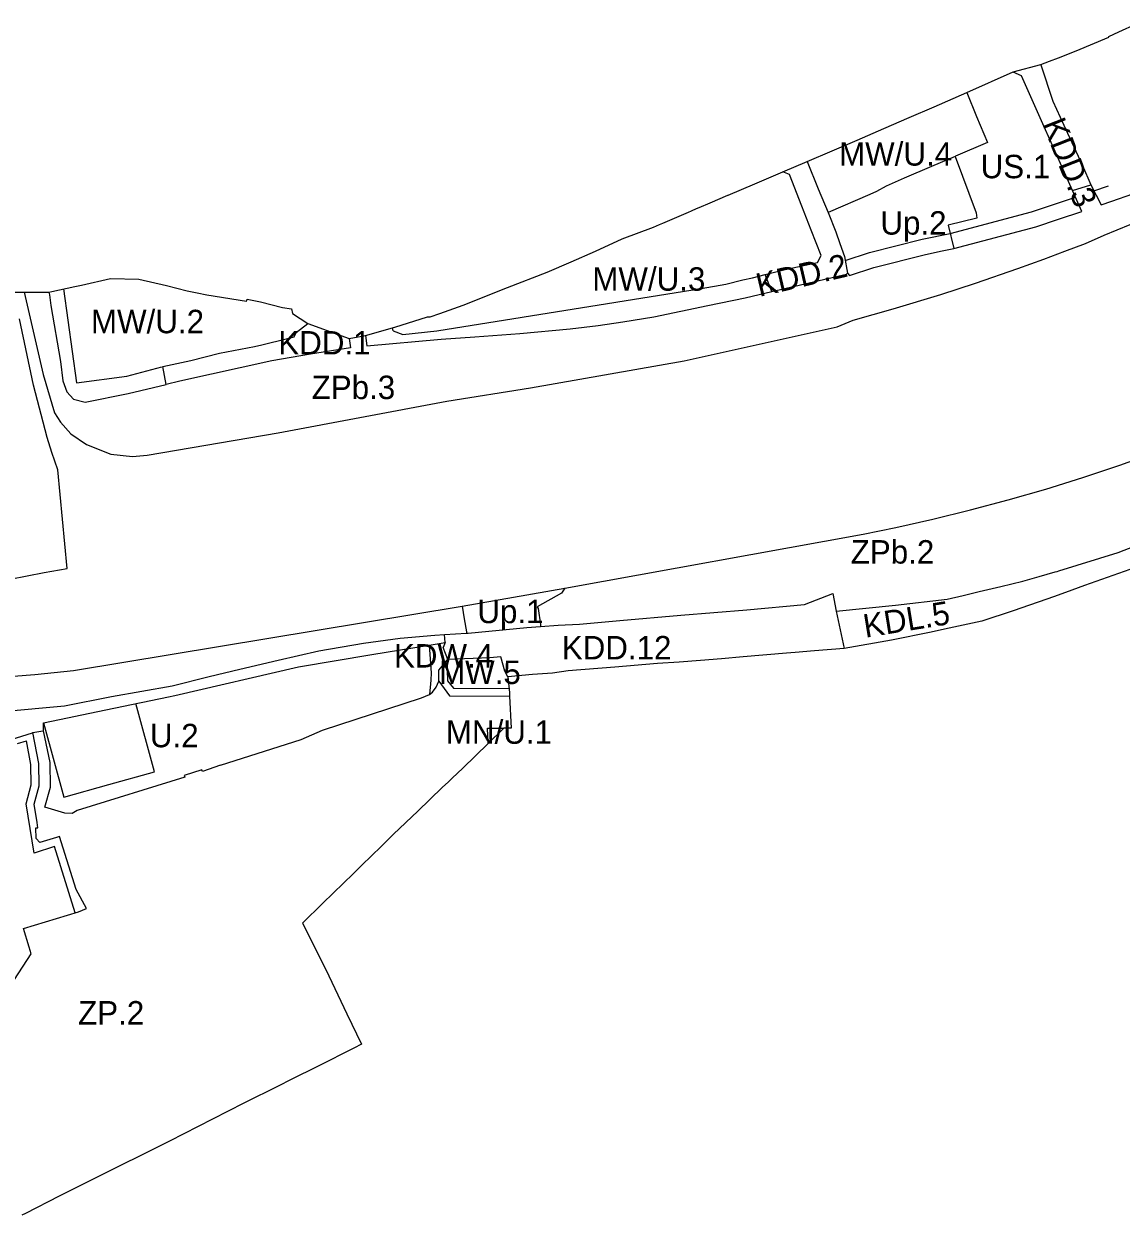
# Model space of a CAD drawing. Extents: x 7421697 to 7426767, y 5545731 to 5547485.
# Drawn here: x 7422364 to 7422926, y 5546353 to 5546963 of the extents above; entities that cross this region are included whole.
import ezdxf

# ---------------------------------------------------------------- set-up
doc = ezdxf.new("R2010")
doc.units = 0
for name, color, linetype in [('LIN_Linia Zabudowy Nieprzekraczalna', 7, 'Continuous'), ('LIN_linie_rozgraniczajace', 7, 'Continuous'), ('TXT_oznaczenia_przeznaczen', 7, 'Continuous')]:
    doc.layers.add(name, color=color, linetype=linetype)

msp = doc.modelspace()

# ---------------------------------------------------------------- linework, layer by layer
at = {"layer": 'LIN_Linia Zabudowy Nieprzekraczalna'}
for p, q in [((7422552.95, 5546806.17), (7422552.52, 5546807.68)), ((7422430.58, 5546580.08), (7422421.03, 5546615.08)), ((7422373.64, 5546605.22), (7422384.13, 5546567.15)), ((7422379.38, 5546541.92), (7422368.99, 5546538.42))]:
    msp.add_line(p, q, dxfattribs=at)
for points in [[(7422912.02, 5546877.8), (7422919.45, 5546880.48)], [(7422784.56, 5546842.21), (7422797.01, 5546846.25), (7422823.98, 5546853.04), (7422838.37, 5546856.05), (7422879.96, 5546867.06), (7422902.55, 5546874.63)], [(7422552.95, 5546806.17), (7422557.83, 5546804.33), (7422575.31, 5546806.09), (7422710.7, 5546827.9), (7422723.35, 5546830.03), (7422732.14, 5546832.22), (7422737.06, 5546833.31), (7422743.59, 5546835.05)], [(7422383.97, 5546827.59), (7422390.58, 5546779.45), (7422416.35, 5546782.97), (7422434.41, 5546787.75)], [(7422580.36, 5546637.67), (7422580.72, 5546626.73), (7422583.84, 5546623.03), (7422612.6, 5546622.89)], [(7422360.46, 5546594.59), (7422365.03, 5546596.05)], [(7422364.77, 5546563.74), (7422367.44, 5546573.55), (7422367.3, 5546583.97), (7422365.03, 5546596.05)], [(7422384.13, 5546567.15), (7422407.22, 5546573.65), (7422430.57, 5546580.08)], [(7422368.99, 5546538.42), (7422364.77, 5546563.74)], [(7422390.01, 5546507.84), (7422379.38, 5546541.92)]]:
    msp.add_lwpolyline(points, dxfattribs=at)
at = {"layer": 'LIN_linie_rozgraniczajace'}
for p, q in [((7422901.03, 5546878.01), (7422910.42, 5546880.92)), ((7422779.9, 5546662.45), (7422783.95, 5546643.35)), ((7422579.51, 5546646.49), (7422579.25, 5546650.51)), ((7422371.29, 5546584.37), (7422368.33, 5546600.22)), ((7422369.8, 5546551.45), (7422370.87, 5546551.46)), ((7422390.46, 5546519.82), (7422381.98, 5546547.01)), ((7422395.72, 5546510.16), (7422390.46, 5546519.82)), ((7422391.68, 5546508.35), (7422395.72, 5546510.16))]:
    msp.add_line(p, q, dxfattribs=at)
for points in [[(7422359.29, 5546825.98), (7422363.8, 5546825.99), (7422376.48, 5546826.02), (7422378.01, 5546826.34), (7422389.74, 5546828.8), (7422393.14, 5546829.48), (7422408.11, 5546832.87), (7422422.58, 5546832.59), (7422436.82, 5546829.38), (7422447.42, 5546826.65), (7422452.4, 5546825.55), (7422457.34, 5546824.66), (7422477.74, 5546821.31), (7422478.02, 5546822.34), (7422484.9, 5546820.92), (7422496.12, 5546818.14), (7422500.8, 5546817.39), (7422501.28, 5546814.95), (7422509.19, 5546809.96), (7422530.44, 5546802.24), (7422538.71, 5546803.82), (7422553.82, 5546808.04), (7422570.53, 5546813.32), (7422571.82, 5546813.37), (7422576.76, 5546815), (7422588.81, 5546819.33), (7422611.54, 5546828.37), (7422631.89, 5546836.15), (7422644.16, 5546841.41), (7422656.62, 5546847.04), (7422670.27, 5546853.34), (7422686.29, 5546859.23), (7422689.43, 5546860.59), (7422691.06, 5546861.3), (7422704.19, 5546866.92), (7422705.7, 5546867.58), (7422708.41, 5546868.77), (7422709.75, 5546869.36), (7422715.28, 5546871.67), (7422715.38, 5546871.71), (7422724.4, 5546875.59), (7422724.5, 5546875.63), (7422738.29, 5546881.5), (7422752.61, 5546887.69), (7422765.06, 5546892.92), (7422790.59, 5546903.9), (7422804.42, 5546909.82), (7422817.34, 5546915.4), (7422830.16, 5546920.97), (7422846.82, 5546928.26), (7422870.58, 5546938.86), (7422884.74, 5546942.56), (7422889.21, 5546944.29), (7422889.26, 5546944.31), (7422893.83, 5546946.09), (7422902.85, 5546949.59), (7422919.59, 5546956.68), (7422919.57, 5546956.95), (7422924.7, 5546959.3), (7422933.83, 5546963.46)], [(7422884.74, 5546942.56), (7422884.81, 5546942.53), (7422890.88, 5546923.79), (7422896.53, 5546911.48), (7422899.44, 5546905.2), (7422906.1, 5546890.86), (7422910.42, 5546880.92), (7422915.71, 5546870.63)], [(7422765.06, 5546892.92), (7422770.75, 5546878.85), (7422775.74, 5546866.79), (7422779.75, 5546856.85), (7422781.84, 5546850.87), (7422784.17, 5546844.28), (7422785.78, 5546835.69), (7422786.67, 5546834.48), (7422799.22, 5546838.56), (7422825.77, 5546845.24), (7422834.31, 5546847.09), (7422840.21, 5546848.26), (7422882.26, 5546859.4), (7422893.76, 5546863.43), (7422905.84, 5546867.3), (7422901.03, 5546878.01), (7422874.81, 5546936.78), (7422870.54, 5546938.73), (7422870.58, 5546938.86)], [(7422906.35, 5546730.92), (7422925.3, 5546737.28), (7422944.22, 5546744.12), (7422962.85, 5546751.36), (7422981.56, 5546758.6), (7422999.8, 5546766.68), (7423018.04, 5546775), (7423037.74, 5546784.62), (7423055.52, 5546793.71), (7423073.17, 5546803.13), (7423090.57, 5546813), (7423107.42, 5546822.96), (7423176.11, 5546867.28), (7423238.37, 5546907.25), (7423275.73, 5546929.87)], [(7422846.82, 5546928.26), (7422851.87, 5546915.91), (7422857.54, 5546902.7), (7422841.02, 5546895.7), (7422840.88, 5546895.5), (7422828.7, 5546890.35), (7422814.81, 5546884.37), (7422805.53, 5546880.21), (7422800.53, 5546877.51), (7422797.12, 5546876.03), (7422775.74, 5546866.79)], [(7422840.88, 5546895.5), (7422851.68, 5546866.61), (7422851.97, 5546863.82), (7422837.23, 5546860.28), (7422840.21, 5546848.26)], [(7422538.71, 5546803.82), (7422539.44, 5546798.41), (7422577.53, 5546801.85), (7422594.76, 5546803.09), (7422617.85, 5546804.8), (7422643.63, 5546807.12), (7422657.97, 5546808.95), (7422670.57, 5546810.7), (7422686.44, 5546813.39), (7422714.11, 5546819.07), (7422733.35, 5546823.01), (7422746.93, 5546826.21), (7422745.61, 5546829.77), (7422743.59, 5546835.05), (7422753.83, 5546837.53), (7422770.36, 5546841.15), (7422772.16, 5546844.67), (7422767.06, 5546857.65), (7422762.38, 5546869.96), (7422755.94, 5546886.18), (7422752.61, 5546887.69)], [(7422915.71, 5546870.63), (7422921.17, 5546872.55), (7422931.97, 5546876.36)], [(7422363.8, 5546825.99), (7422373.61, 5546783.76), (7422379.4, 5546764.19), (7422382.45, 5546759.31), (7422387.65, 5546753.42), (7422395.68, 5546747.84), (7422408.19, 5546742.89), (7422419.35, 5546741.69), (7422426.92, 5546742.5), (7422494.01, 5546753.83), (7422580.32, 5546770.04), (7422623.27, 5546776.99), (7422701.98, 5546790.69), (7422780.43, 5546808.14), (7422788.69, 5546811.54), (7422809.16, 5546817.39), (7422833.5, 5546824.82), (7422851.24, 5546830.53), (7422872.94, 5546838.07), (7422886.3, 5546842.92), (7422897.09, 5546846.92), (7422907.65, 5546850.84), (7422917.18, 5546855.08), (7422930.57, 5546860.54)], [(7422746.93, 5546826.21), (7422785.18, 5546835.19), (7422785.78, 5546835.69)], [(7422376.48, 5546826.02), (7422376.8, 5546824.55), (7422377.52, 5546819.19), (7422382.4, 5546790.5), (7422383.6, 5546780.47), (7422385.63, 5546774.85), (7422389.13, 5546771.09), (7422395.1, 5546769.53), (7422417.03, 5546774.02), (7422436.58, 5546778.7)], [(7422356.71, 5546678.9), (7422374.12, 5546682.31), (7422385.81, 5546684.28), (7422381.12, 5546734.93), (7422378.02, 5546743.7), (7422375.67, 5546751.44), (7422368.67, 5546778.27), (7422361.35, 5546812.29)], [(7422530.44, 5546802.24), (7422530.99, 5546797.43), (7422510.48, 5546794.11), (7422490.7, 5546790.74), (7422443.66, 5546780.28), (7422436.58, 5546778.7), (7422434.85, 5546787.86), (7422449.19, 5546790.99), (7422463.91, 5546794.65), (7422481.82, 5546798.11), (7422485.61, 5546799.01), (7422498.73, 5546802.16), (7422502.23, 5546803), (7422503.17, 5546805.3), (7422509.19, 5546809.96)], [(7422640.88, 5546674.26), (7422793.72, 5546701.86), (7422810.45, 5546705.33), (7422829.36, 5546709.57), (7422848.78, 5546714.35), (7422868.09, 5546719.46), (7422887.27, 5546724.95), (7422906.35, 5546730.92)], [(7422352.71, 5546611.01), (7422384.46, 5546613.98), (7422408.52, 5546618.82), (7422439.62, 5546624.16), (7422458.67, 5546628.91), (7422474.35, 5546632.69), (7422493.94, 5546637.43), (7422514.76, 5546642.18), (7422537.75, 5546646.14), (7422556.51, 5546648.69), (7422574.3, 5546650.19), (7422579.25, 5546650.51), (7422590.56, 5546651.23), (7422591.37, 5546651.28), (7422621.34, 5546654.04), (7422628.45, 5546654.56), (7422637.46, 5546655.22), (7422648.41, 5546655.88), (7422669.03, 5546657.76), (7422700.27, 5546660.47), (7422734.16, 5546663.14), (7422763.75, 5546665.83), (7422778.13, 5546671.45), (7422779.9, 5546662.45), (7422810.23, 5546665.63), (7422836.74, 5546668.63), (7422844.95, 5546670.58), (7422853.16, 5546672.52), (7422864.36, 5546675.19), (7422875.56, 5546677.85), (7422883.87, 5546680.24), (7422892.17, 5546682.62), (7422893.12, 5546682.88), (7422894.07, 5546683.15), (7422924.37, 5546692.51), (7422938.15, 5546697.79)], [(7422930.31, 5546683.88), (7422907.12, 5546675.71), (7422900.64, 5546673.26), (7422891.87, 5546669.93), (7422870.56, 5546662.69), (7422854.6, 5546657.28), (7422835.45, 5546653.18), (7422828.61, 5546651.71), (7422808.31, 5546647.6), (7422783.95, 5546643.35), (7422768.83, 5546642.12), (7422758.97, 5546641.29), (7422754.5, 5546640.94), (7422732.24, 5546639.12), (7422721.2, 5546638.01), (7422710.35, 5546637.22), (7422699.53, 5546636.27), (7422688.36, 5546635.74), (7422666.55, 5546633.78), (7422642.6, 5546631.86), (7422634.54, 5546630.74), (7422624.22, 5546630.1), (7422611.72, 5546628.83), (7422612.48, 5546620.85), (7422612.59, 5546618.89), (7422613.4, 5546602.45), (7422609.66, 5546602.48), (7422601.65, 5546594.65), (7422588.56, 5546582), (7422583.22, 5546576.87), (7422581.32, 5546575.07), (7422578.02, 5546572.03), (7422565.5, 5546560.03), (7422553.06, 5546548.18), (7422546.7, 5546541.82), (7422541.78, 5546537.16), (7422536.92, 5546532.39), (7422532.36, 5546527.8), (7422527.52, 5546523.03), (7422516.8, 5546512.79), (7422506.41, 5546502.64), (7422517.23, 5546481.24), (7422519.95, 5546475.55), (7422529.16, 5546456.21), (7422536.64, 5546440.52), (7422532.73, 5546438.52), (7422514.39, 5546429.29), (7422500.28, 5546422.24), (7422494.24, 5546419.24), (7422476.45, 5546410.33), (7422460.34, 5546402.21), (7422438.35, 5546390.86), (7422398.84, 5546371.27), (7422381.83, 5546362.61), (7422364.42, 5546353.84), (7422362.57, 5546352.95)], [(7422347.08, 5546629.23), (7422349.4, 5546628.48), (7422369.29, 5546630), (7422389.04, 5546631.99), (7422588.25, 5546665.06), (7422640.88, 5546674.26)], [(7422640.88, 5546674.26), (7422639.24, 5546671.67), (7422626.66, 5546664.62), (7422627.28, 5546663.84), (7422628.38, 5546655.65), (7422628.45, 5546654.56)], [(7422588.25, 5546665.06), (7422589.27, 5546658.53), (7422590.45, 5546651.84), (7422590.56, 5546651.23)], [(7422373.74, 5546601.23), (7422373.64, 5546605.22), (7422405.7, 5546611.89), (7422437.75, 5546618.56), (7422440.99, 5546619.31), (7422504.31, 5546633.91), (7422541.91, 5546640.2), (7422571.27, 5546645.11), (7422579.51, 5546646.49), (7422578.59, 5546643.81)], [(7422571.27, 5546645.11), (7422572.38, 5546630.95), (7422572.23, 5546627.05), (7422571.49, 5546619.71)], [(7422611.72, 5546628.83), (7422610.1, 5546631.81), (7422608.14, 5546639.01), (7422602.41, 5546638.6), (7422580.84, 5546637.64), (7422578.59, 5546643.81)], [(7422464.38, 5546583.59), (7422505.78, 5546596.63), (7422516.61, 5546601.56), (7422567.46, 5546618.1), (7422571.49, 5546619.71), (7422573.11, 5546620.94), (7422574.99, 5546623.49), (7422576.27, 5546626.65), (7422576.39, 5546632.23), (7422580.84, 5546637.64)], [(7422576.27, 5546626.65), (7422581.79, 5546619.04), (7422612.59, 5546618.89)], [(7422357.16, 5546596.69), (7422368.06, 5546600.16), (7422368.33, 5546600.22), (7422372.39, 5546600.92), (7422373.74, 5546601.23)], [(7422374.44, 5546562.03), (7422377.24, 5546572.31), (7422377.06, 5546585), (7422373.74, 5546601.23)], [(7422601.65, 5546594.65), (7422601.26, 5546602.58), (7422609.66, 5546602.48)], [(7422368.86, 5546563.54), (7422371.45, 5546573.04), (7422371.29, 5546584.37)], [(7422464.38, 5546583.59), (7422455.16, 5546580.37), (7422454.92, 5546581.13), (7422445.89, 5546578.33)], [(7422445.89, 5546578.33), (7422446.18, 5546577.36), (7422390.94, 5546560.35), (7422388.41, 5546558.87), (7422384.66, 5546559), (7422374.44, 5546562.03)], [(7422370.87, 5546551.46), (7422370.41, 5546554.25), (7422368.86, 5546563.54)], [(7422371.8, 5546543.88), (7422369.89, 5546546.05), (7422369.8, 5546551.45)], [(7422381.98, 5546547.01), (7422380.31, 5546546.53), (7422371.8, 5546543.88)], [(7422322.79, 5546430.84), (7422334.12, 5546436.39), (7422341.69, 5546447.48), (7422367.46, 5546486.8), (7422366.38, 5546490.34), (7422363.49, 5546499.79), (7422391.68, 5546508.35)]]:
    msp.add_lwpolyline(points, dxfattribs=at)

# ---------------------------------------------------------------- texts
at = {"layer": 'TXT_oznaczenia_przeznaczen'}
for s, rotation, p in [('KDD.3', 291.47726, (7422885.4, 5546912.31)), ('KDD.2', 13.02751, (7422740.48, 5546823.47)), ('KDL.5', 9.17901, (7422794.83, 5546648.82))]:
    msp.add_text(s, height=12, rotation=rotation, dxfattribs=at).set_placement(p)
for s, p in [('MW/U.4', (7422781.38, 5546890.8)), ('US.1', (7422853.94, 5546884.33)), ('Up.2', (7422802.57, 5546855.44)), ('MW/U.3', (7422654.95, 5546826.69)), ('MW/U.2', (7422398.05, 5546804.91)), ('KDD.1', (7422494.06, 5546794.01)), ('ZPb.3', (7422511.14, 5546771.16)), ('ZPb.2', (7422787.37, 5546686.87)), ('Up.1', (7422596.05, 5546656.33)), ('KDD.12', (7422639.32, 5546637.76)), ('KDW.4', (7422553.32, 5546633.59)), ('MW.5', (7422576.41, 5546625.14)), ('MN/U.1', (7422579.91, 5546594.51)), ('U.2', (7422428.26, 5546592.74)), ('ZP.2', (7422391.46, 5546450.66))]:
    msp.add_text(s, height=12, dxfattribs=at).set_placement(p)

doc.saveas('drawing.dxf')
